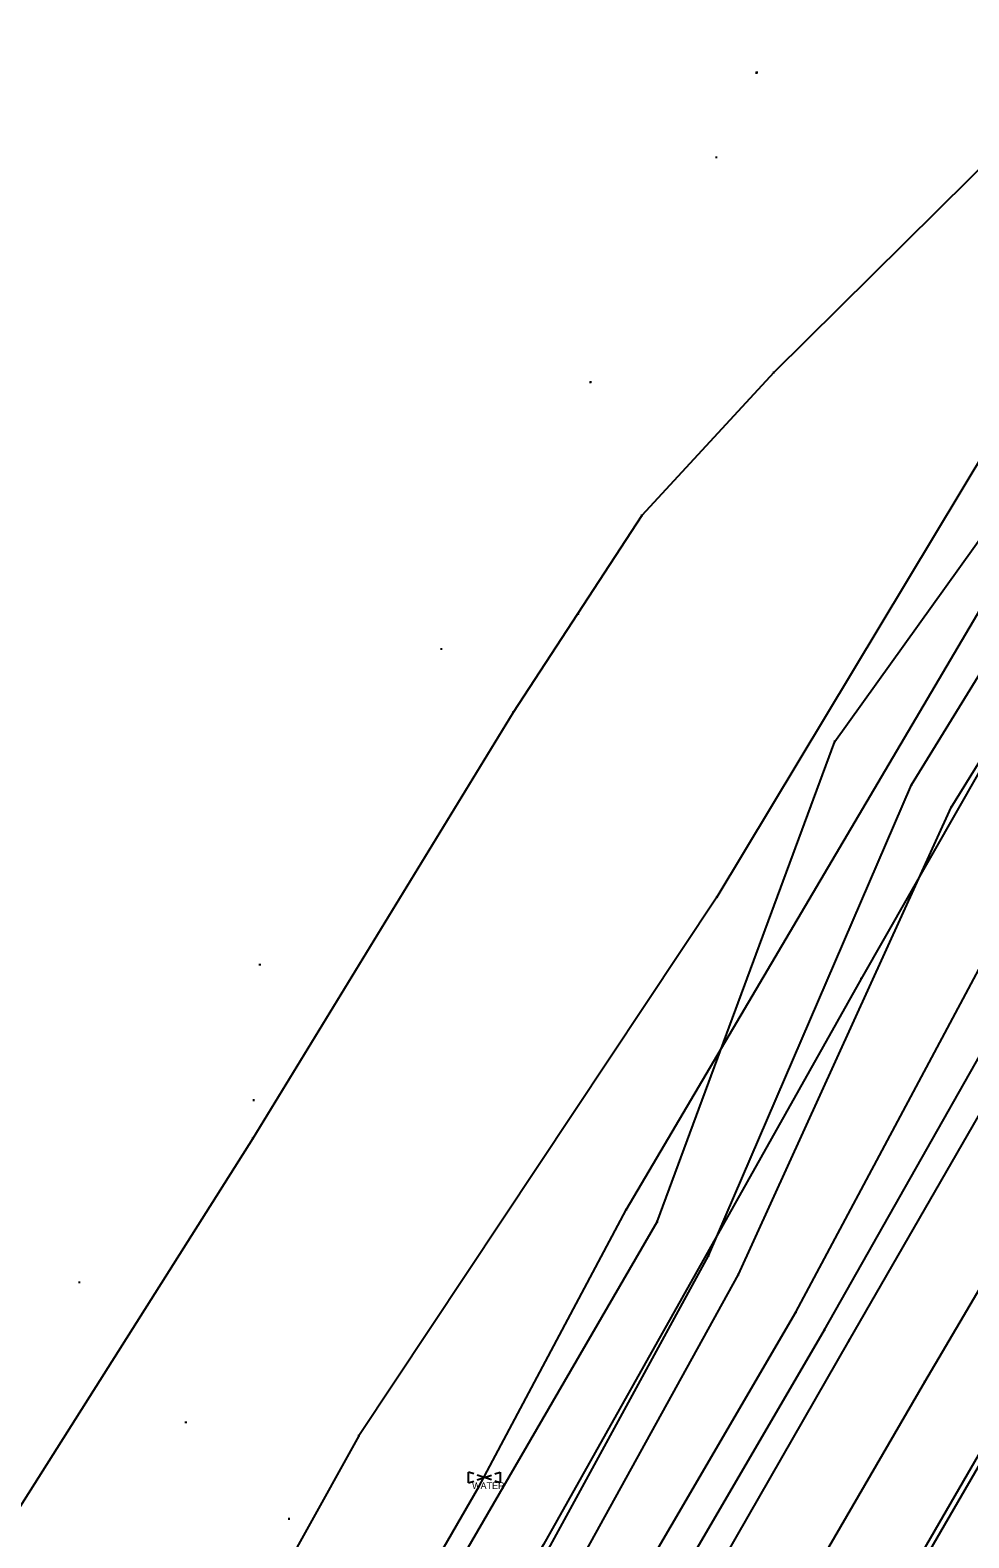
# Model space of a CAD drawing. Extents: x 1954856 to 2011933, y 399149 to 426294.
# Drawn here: x 2006880.9 to 2007013.7, y 402945.3 to 403158.5 of the extents above; entities that cross this region are included whole.
import ezdxf

# ---------------------------------------------------------------- set-up
doc = ezdxf.new("R2010")
doc.units = 0
for name, color, linetype in [('BankMent_ep', 7, 'Continuous'), ('BaselineSurvey', 7, 'Continuous'), ('GroundShot_ep', 7, 'Continuous'), ('PavtAsphalt_ep', 7, 'Continuous'), ('PavtAsphaltCrown_ep', 7, 'Continuous'), ('PMRK_ep', 7, 'Continuous'), ('PointLocator_ep', 7, 'Continuous'), ('SanitaryFM_B_ep', 7, 'Continuous'), ('ShldrPaved_ep', 7, 'Continuous'), ('ValveWater_ep', 7, 'Continuous'), ('WaterA_ep', 7, 'Continuous'), ('WaterNP_B_ep', 7, 'Continuous')]:
    doc.layers.add(name, color=color, linetype=linetype)

msp = doc.modelspace()

# ---------------------------------------------------------------- linework, layer by layer
at = {"layer": 'BankMent_ep'}
for points in [[(2006869.83, 402816.84), (2006917.12, 402899.63), (2006969.57, 402989.98), (2006994.68, 403057.89), (2007051.63, 403137.3), (2007132.84, 403259.49), (2007135.77, 403271.99)], [(2006889.4, 402803.93), (2006936.59, 402887.08), (2006989.2, 402977.17), (2007023.21, 403040.92), (2007073.66, 403123), (2007149.61, 403250.93), (2007152.62, 403257.36)], [(2006879.57, 402809.17), (2006926.76, 402893.37), (2006976.82, 402985.18), (2007005.56, 403051.76), (2007055.72, 403133.31), (2007139.59, 403255.51)], [(2006884.3, 402806.75), (2006930.41, 402890.65), (2006981.05, 402982.51), (2007011.13, 403048.59), (2007061.27, 403129.56), (2007144.61, 403253.21)]]:
    msp.add_lwpolyline(points, dxfattribs=at)
at = {"layer": 'BaselineSurvey'}
msp.add_lwpolyline([(2006095.1, 401364.22), (2006751.44, 402500.64), (2007687.69, 404121.69)], dxfattribs=at)
at = {"layer": 'GroundShot_ep'}
for p, q in [((2006978.07, 403140.53), (2006977.82, 403140.53)), ((2006977.94, 403140.41), (2006977.94, 403140.66)), ((2006977.94, 403140.53), (2006977.94, 403140.53)), ((2006960.28, 403108.73), (2006960.03, 403108.73)), ((2006960.16, 403108.6), (2006960.16, 403108.85)), ((2006960.16, 403108.73), (2006960.16, 403108.73)), ((2006958.53, 403075.97), (2006958.28, 403075.97)), ((2006958.4, 403075.84), (2006958.4, 403076.09)), ((2006958.4, 403075.97), (2006958.4, 403075.97)), ((2006939.18, 403070.98), (2006938.93, 403070.98)), ((2006939.06, 403070.86), (2006939.06, 403071.11)), ((2006939.06, 403070.98), (2006939.06, 403070.98)), ((2006913.52, 403026.34), (2006913.27, 403026.34)), ((2006913.39, 403026.22), (2006913.39, 403026.47)), ((2006913.39, 403026.34), (2006913.39, 403026.34)), ((2006912.63, 403007.16), (2006912.38, 403007.16)), ((2006912.5, 403007.03), (2006912.5, 403007.28)), ((2006912.5, 403007.16), (2006912.5, 403007.16)), ((2006887.96, 402981.41), (2006887.71, 402981.41)), ((2006887.84, 402981.28), (2006887.84, 402981.53)), ((2006887.84, 402981.41), (2006887.84, 402981.41)), ((2006902.91, 402961.49), (2006902.91, 402961.74)), ((2006903.04, 402961.61), (2006902.79, 402961.61)), ((2006902.91, 402961.61), (2006902.91, 402961.61)), ((2006917.63, 402947.97), (2006917.38, 402947.97)), ((2006917.51, 402947.84), (2006917.51, 402948.09)), ((2006917.51, 402947.97), (2006917.51, 402947.97))]:
    msp.add_line(p, q, dxfattribs=at)
at = {"layer": 'PavtAsphalt_ep'}
msp.add_lwpolyline([(2006897.05, 402800.14), (2006944.17, 402881.58), (2006996.71, 402973.18), (2007032.59, 403035.44), (2007081.34, 403118.81), (2007155.79, 403247.38), (2007202.92, 403329.48)], dxfattribs=at)
at = {"layer": 'PavtAsphaltCrown_ep'}
msp.add_lwpolyline([(2006917.74, 402787.19), (2006964.28, 402867.82), (2007017.94, 402960.42), (2007054.7, 403023.68), (2007102.51, 403106.5), (2007177.29, 403236.13), (2007223.74, 403317.44)], dxfattribs=at)
at = {"layer": 'PMRK_ep'}
msp.add_lwpolyline([(2006907.45, 402793.37), (2006954.17, 402875.59), (2007007.43, 402967.36), (2007044.03, 403029.48), (2007091.72, 403112.9), (2007166.49, 403241.69), (2007213.16, 403323.66)], dxfattribs=at)
at = {"layer": 'PointLocator_ep'}
for p, q in [((2006983.75, 403152.49), (2006983.5, 403152.49)), ((2006983.79, 403152.55), (2006983.54, 403152.55)), ((2006983.62, 403152.36), (2006983.62, 403152.61)), ((2006983.62, 403152.49), (2006983.62, 403152.49)), ((2006983.67, 403152.42), (2006983.67, 403152.67)), ((2006983.67, 403152.55), (2006983.67, 403152.55)), ((2006986.17, 403110.09), (2006985.92, 403110.09)), ((2006986.05, 403109.97), (2006986.05, 403110.22)), ((2006986.05, 403110.09), (2006986.05, 403110.09)), ((2006967.52, 403089.86), (2006967.27, 403089.86)), ((2006967.4, 403089.73), (2006967.4, 403089.98)), ((2006967.4, 403089.86), (2006967.4, 403089.86)), ((2006949.3, 403062), (2006949.05, 403062)), ((2006949.18, 403061.87), (2006949.18, 403062.12)), ((2006949.18, 403062), (2006949.18, 403062)), ((2006994.8, 403057.89), (2006994.55, 403057.89)), ((2006994.68, 403057.77), (2006994.68, 403058.02)), ((2006994.68, 403057.89), (2006994.68, 403057.89)), ((2007005.69, 403051.76), (2007005.44, 403051.76)), ((2007005.56, 403051.64), (2007005.56, 403051.89)), ((2007005.56, 403051.76), (2007005.56, 403051.76)), ((2007011.25, 403048.59), (2007011, 403048.59)), ((2007011.13, 403048.46), (2007011.13, 403048.71)), ((2007011.13, 403048.59), (2007011.13, 403048.59)), ((2006978.14, 403035.87), (2006977.89, 403035.87)), ((2006978.01, 403035.74), (2006978.01, 403035.99)), ((2006978.01, 403035.87), (2006978.01, 403035.87)), ((2006998.53, 403024.32), (2006998.28, 403024.32)), ((2006998.4, 403024.19), (2006998.4, 403024.44)), ((2006998.4, 403024.32), (2006998.4, 403024.32)), ((2006912.52, 403001.77), (2006912.27, 403001.77)), ((2006912.39, 403001.64), (2006912.39, 403001.89)), ((2006912.39, 403001.77), (2006912.39, 403001.77)), ((2006965.32, 402991.67), (2006965.07, 402991.67)), ((2006965.19, 402991.55), (2006965.19, 402991.8)), ((2006965.19, 402991.67), (2006965.19, 402991.67)), ((2006969.69, 402989.98), (2006969.44, 402989.98)), ((2006969.57, 402989.85), (2006969.57, 402990.1)), ((2006969.57, 402989.98), (2006969.57, 402989.98)), ((2006976.95, 402985.18), (2006976.7, 402985.18)), ((2006976.82, 402985.06), (2006976.82, 402985.31)), ((2006976.82, 402985.18), (2006976.82, 402985.18)), ((2006981.18, 402982.51), (2006980.93, 402982.51)), ((2006981.05, 402982.39), (2006981.05, 402982.64)), ((2006981.05, 402982.51), (2006981.05, 402982.51)), ((2006989.33, 402977.17), (2006989.08, 402977.17)), ((2006989.2, 402977.05), (2006989.2, 402977.3)), ((2006989.2, 402977.17), (2006989.2, 402977.17)), ((2006993.36, 402974.68), (2006993.11, 402974.68)), ((2006993.23, 402974.55), (2006993.23, 402974.8)), ((2006993.23, 402974.68), (2006993.23, 402974.68)), ((2006996.84, 402973.18), (2006996.59, 402973.18)), ((2006996.71, 402973.05), (2006996.71, 402973.3)), ((2006996.71, 402973.18), (2006996.71, 402973.18)), ((2007007.55, 402967.36), (2007007.3, 402967.36)), ((2007007.43, 402967.24), (2007007.43, 402967.49)), ((2007007.43, 402967.36), (2007007.43, 402967.36)), ((2006927.49, 402959.7), (2006927.24, 402959.7)), ((2006927.36, 402959.58), (2006927.36, 402959.83)), ((2006927.36, 402959.7), (2006927.36, 402959.7)), ((2006944.46, 402952.47), (2006944.21, 402952.47)), ((2006944.33, 402952.34), (2006944.33, 402952.59)), ((2006944.33, 402952.47), (2006944.33, 402952.47))]:
    msp.add_line(p, q, dxfattribs=at)
at = {"layer": 'SanitaryFM_B_ep'}
for points in [[(2007401.95, 403818.63), (2007312.3, 403645.73), (2007290.75, 403604.1), (2007263.4, 403556.68), (2007243.69, 403523.41), (2007211.46, 403477.24), (2007146.71, 403360.43), (2007074.94, 403233.14), (2007057.11, 403197.22), (2007018.41, 403142.13), (2006986.05, 403110.09), (2006967.4, 403089.86), (2006949.18, 403062), (2006912.39, 403001.77), (2006860.92, 402920.48), (2006691.88, 402620.5), (2006600.9, 402464.44), (2006520.64, 402315.09), (2006403, 402102.49), (2006392.62, 402085.16), (2006366.88, 402033.22), (2006268.08, 401998.8), (2006240.51, 401985.14), (2006227.32, 401976.32)], [(2007078.74, 403198.4), (2007031.79, 403125.31), (2006978.01, 403035.87), (2006927.36, 402959.7), (2006863.76, 402845.21), (2006819, 402760.68), (2006799.33, 402721.33), (2006714.07, 402569.46), (2006673.75, 402500.47), (2006641.55, 402441.62), (2006575.62, 402322.42), (2006531.09, 402244.15), (2006469.22, 402134.35), (2006427.42, 402069.13), (2006371.5, 401989.4)]]:
    msp.add_lwpolyline(points, dxfattribs=at)
at = {"layer": 'ShldrPaved_ep'}
msp.add_lwpolyline([(2006893.49, 402802.15), (2006940.39, 402884.06), (2006993.23, 402974.68), (2007029.04, 403037.85), (2007077.77, 403120.89), (2007151.52, 403249.54), (2007159.58, 403264.32)], dxfattribs=at)
at = {"layer": 'ValveWater_ep'}
for p, q in [((2006943.63, 402954.31), (2006942.88, 402954.56)), ((2006942.88, 402953.06), (2006942.88, 402954.56)), ((2006942.88, 402953.06), (2006943.63, 402953.31)), ((2006946.13, 402953.48), (2006944.13, 402954.15)), ((2006944.13, 402953.48), (2006946.13, 402954.15)), ((2006945.13, 402953.81), (2006945.13, 402953.81)), ((2006946.63, 402954.31), (2006947.38, 402954.56)), ((2006947.38, 402953.06), (2006946.63, 402953.31)), ((2006947.38, 402954.56), (2006947.38, 402953.06))]:
    msp.add_line(p, q, dxfattribs=at)
at = {"layer": 'WaterA_ep'}
msp.add_lwpolyline([(2007183.71, 403343.35), (2007159.89, 403302.21), (2007091.06, 403185.8), (2007048.72, 403112.53), (2006998.4, 403024.32), (2006953.5, 402944.34), (2006900.79, 402854.48), (2006848.29, 402761.17), (2006824.2, 402718.39), (2006722.16, 402548.68), (2006655.5, 402430.73), (2006588.72, 402313.14), (2006543.83, 402235.68), (2006485.84, 402127.23), (2006385.47, 401948.84)], dxfattribs=at)
at = {"layer": 'WaterNP_B_ep'}
msp.add_lwpolyline([(2006433.99, 402042.9), (2006456.16, 402086.4), (2006478.36, 402126.14), (2006495.22, 402164.8), (2006504.71, 402186.55), (2006528.24, 402222.08), (2006572.35, 402300.58), (2006631.69, 402409.75), (2006664.85, 402468.85), (2006775.08, 402656.4), (2006826.97, 402745.97), (2006874.88, 402831.28), (2006921.38, 402912.75), (2006944.33, 402952.47), (2006965.19, 402991.67), (2007050.42, 403136.24), (2007082.62, 403193.93), (2007116.1, 403252.38), (2007160.14, 403327.81), (2007179.84, 403361.08), (2007198.99, 403394.85)], dxfattribs=at)

# ---------------------------------------------------------------- texts
at = {"layer": 'ValveWater_ep'}
msp.add_text('WATER', height=0.95, dxfattribs=at).set_placement((2006943.39, 402952.17))

doc.saveas('drawing.dxf')
